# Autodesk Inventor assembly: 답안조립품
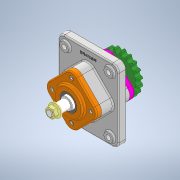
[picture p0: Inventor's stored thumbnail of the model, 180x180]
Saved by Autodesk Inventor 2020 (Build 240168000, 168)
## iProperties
Created: 2021-07
Part Number: 답안조립품
Document SubType Name: Assembly
Designer: Owner
Author: Owner
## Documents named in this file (16)
- C:\Users\Owner\Desktop\710707V1004\710707V1004\답안조립품.iam
- C:\Users\Owner\Desktop\710707V1004\710707V1004\본체.ipt
- C:\Users\Owner\Desktop\710707V1004\710707V1004\M16 너트.ipt
- C:\Users\Owner\Desktop\710707V1004\710707V1004\Ű 6x6x18.ipt
- C:\Users\Owner\Desktop\710707V1004\710707V1004\Ű 6x6x20.ipt
- C:\Users\Owner\Desktop\710707V1004\710707V1004\V-벨트풀리.ipt
- C:\Users\Owner\Desktop\710707V1004\710707V1004\베어링 6206.ipt
- C:\Users\Owner\Desktop\710707V1004\710707V1004\볼트 M6.ipt
- C:\Users\Owner\Desktop\710707V1004\710707V1004\부시.ipt
- C:\Users\Owner\Desktop\710707V1004\710707V1004\오일실 30x42x8.ipt
- C:\Users\Owner\Desktop\710707V1004\710707V1004\오일실 30x45x8.ipt
- C:\Users\Owner\Desktop\710707V1004\710707V1004\체인 스프로킷.ipt
- C:\Users\Owner\Desktop\710707V1004\710707V1004\축.ipt
- C:\Users\Owner\Desktop\710707V1004\710707V1004\커버A.ipt
- C:\Users\Owner\Desktop\710707V1004\710707V1004\커버B.ipt
- C:\Users\Owner\Desktop\710707V1004\710707V1004\멈춤나사 M4.ipt
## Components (4 placed, 3 different names)
1. M16 너트:1
2. Ű 6x6x20:1
3. V-벨트풀리:1
4. M16 너트:2
